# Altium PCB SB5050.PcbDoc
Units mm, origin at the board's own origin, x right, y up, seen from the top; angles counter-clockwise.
Board outline 50 x 50 mm, 2 copper layers (Top Layer, Bottom Layer); 0 components, 0 nets, 4 pads, 0 vias.
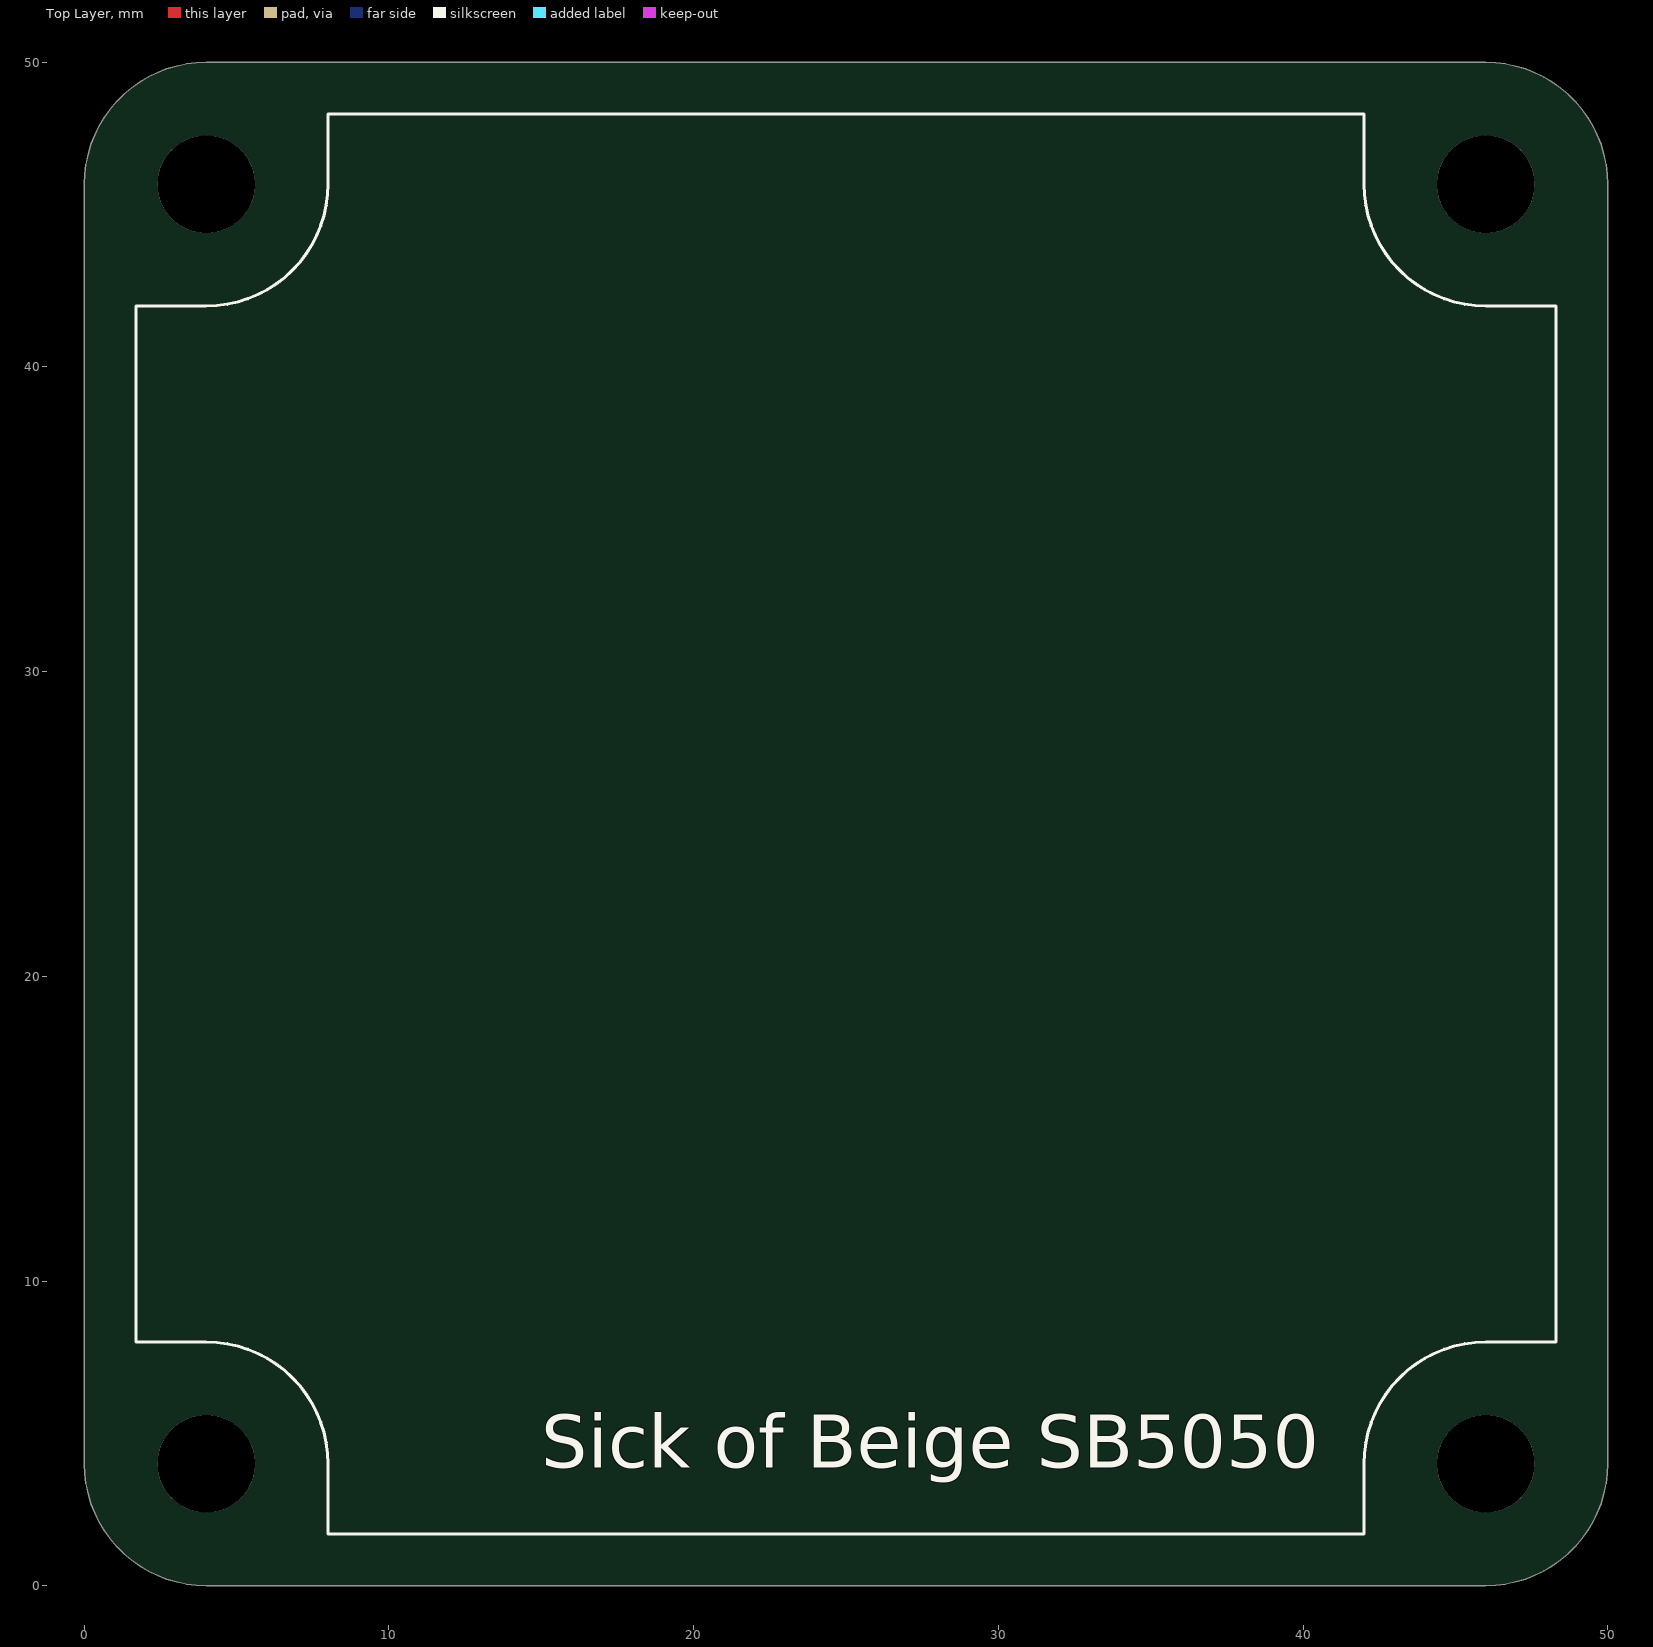
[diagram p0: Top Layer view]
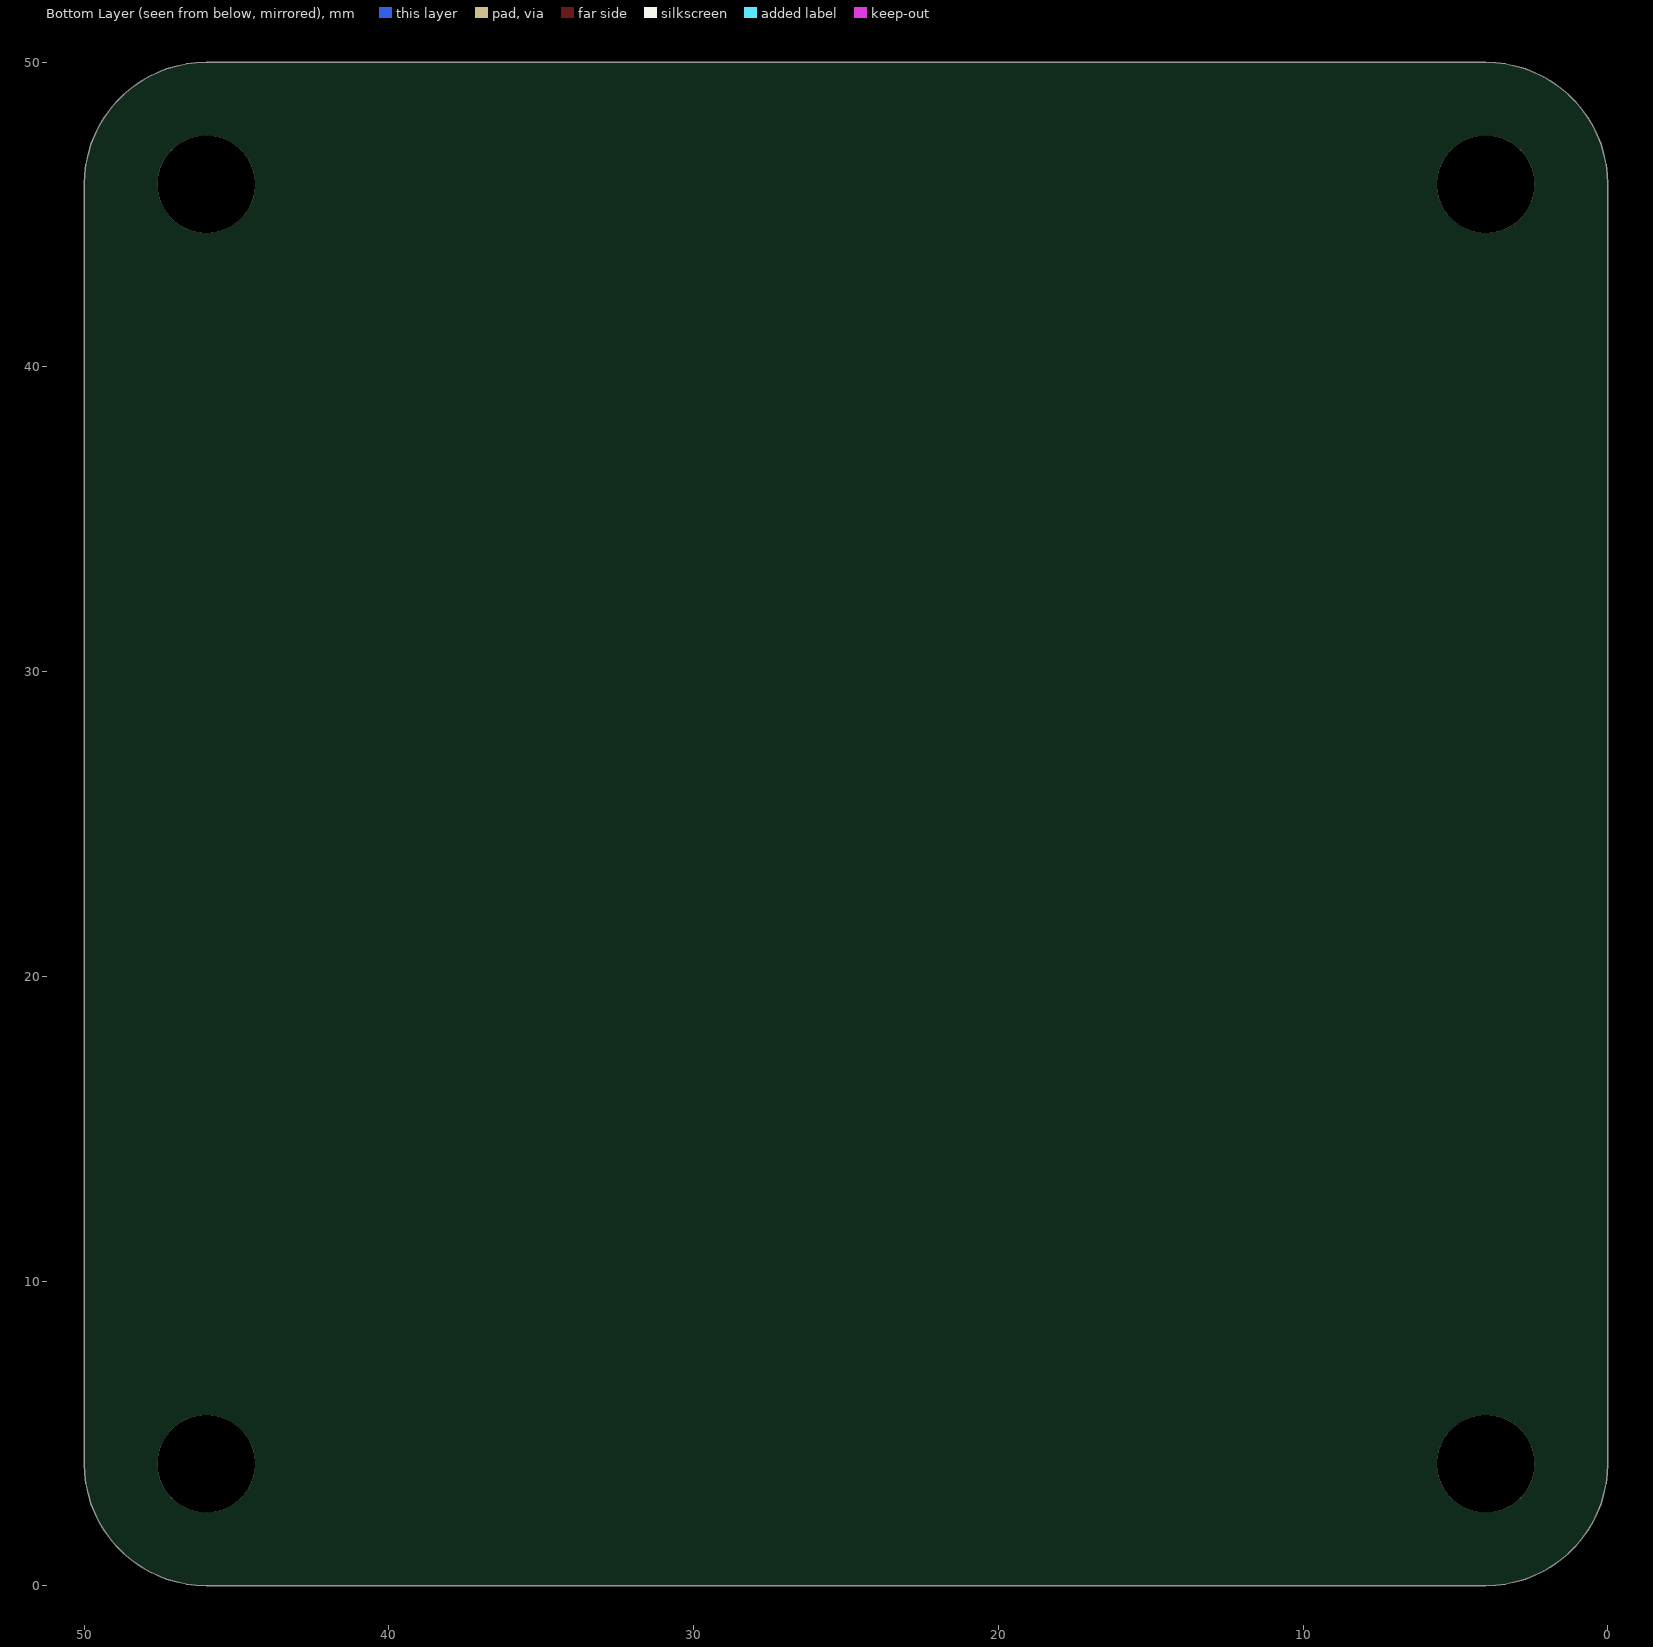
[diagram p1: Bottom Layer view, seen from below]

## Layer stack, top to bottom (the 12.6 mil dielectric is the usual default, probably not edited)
Top Layer: signal copper 0.0356
Dielectric: dielectric 0.32, FR-4, Dk 4.8
Bottom Layer: signal copper 0.0356

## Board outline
4,0 cw(c4,4) 0,4 0,46 cw(c4,46) 4,50 46,50 cw(c46,46) 50,46 50,4 cw(c46,4) 46,0

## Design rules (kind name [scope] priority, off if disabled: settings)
Clearance [All] p1: gap=0.254
PolygonConnect [All] p1: connectstyle=Relief reliefconductorwidth=0.254 reliefentries=4 polygonreliefangle="90 Angle" airgapwidth=0.254
RoutingVias [All] p1: holewidth=0.711 width=1.27 viastyle="Through Hole" minholewidth=0.711 minwidth=1.27 maxholewidth=0.711 maxwidth=1.27
SolderMaskExpansion [All] p1: expansion=0.102
Width [All] p1: maxlimit=0.254 minlimit=0.254 preferedwidth=0.254
28 further rules are at their usual default settings.

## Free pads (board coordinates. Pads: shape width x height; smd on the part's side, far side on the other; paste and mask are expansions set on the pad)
  round 3.2 hole 3.2 unplated: 0(4,4) 1(4,46) 2(46,46) 3(46,4)

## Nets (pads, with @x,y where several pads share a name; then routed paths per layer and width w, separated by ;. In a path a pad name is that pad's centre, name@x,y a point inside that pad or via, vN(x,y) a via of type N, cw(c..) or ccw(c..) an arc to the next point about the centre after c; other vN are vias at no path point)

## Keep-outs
Top Overlay:
  lines w0.102: 1.7,8 4,8 cw(c4,4) 8,4 8,1.7 42,1.7 42,4 cw(c46,4) 46,8 48.3,8 48.3,42 46,42 cw(c46,46) 42,46 42,48.3 8,48.3 8,46 cw(c4,46) 4,42 1.7,42 1.7,8

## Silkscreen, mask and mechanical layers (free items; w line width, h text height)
Top Overlay:
  text "Sick of Beige SB5050" at 15,3.3 h3
Mechanical 1:
  the board outline again, w0.102
Mechanical 4:
  circle w0.102: c46,46 r1.6
  circle w0.102: c4,46 r1.6
  circle w0.102: c4,4 r1.6
  circle w0.102: c46,4 r1.6
  lines w0.102: 0,25 50,25 ; 25,0 25,50

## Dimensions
46,50 to 46,0 on Mechanical 3
0,4 to 50,4 on Mechanical 3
